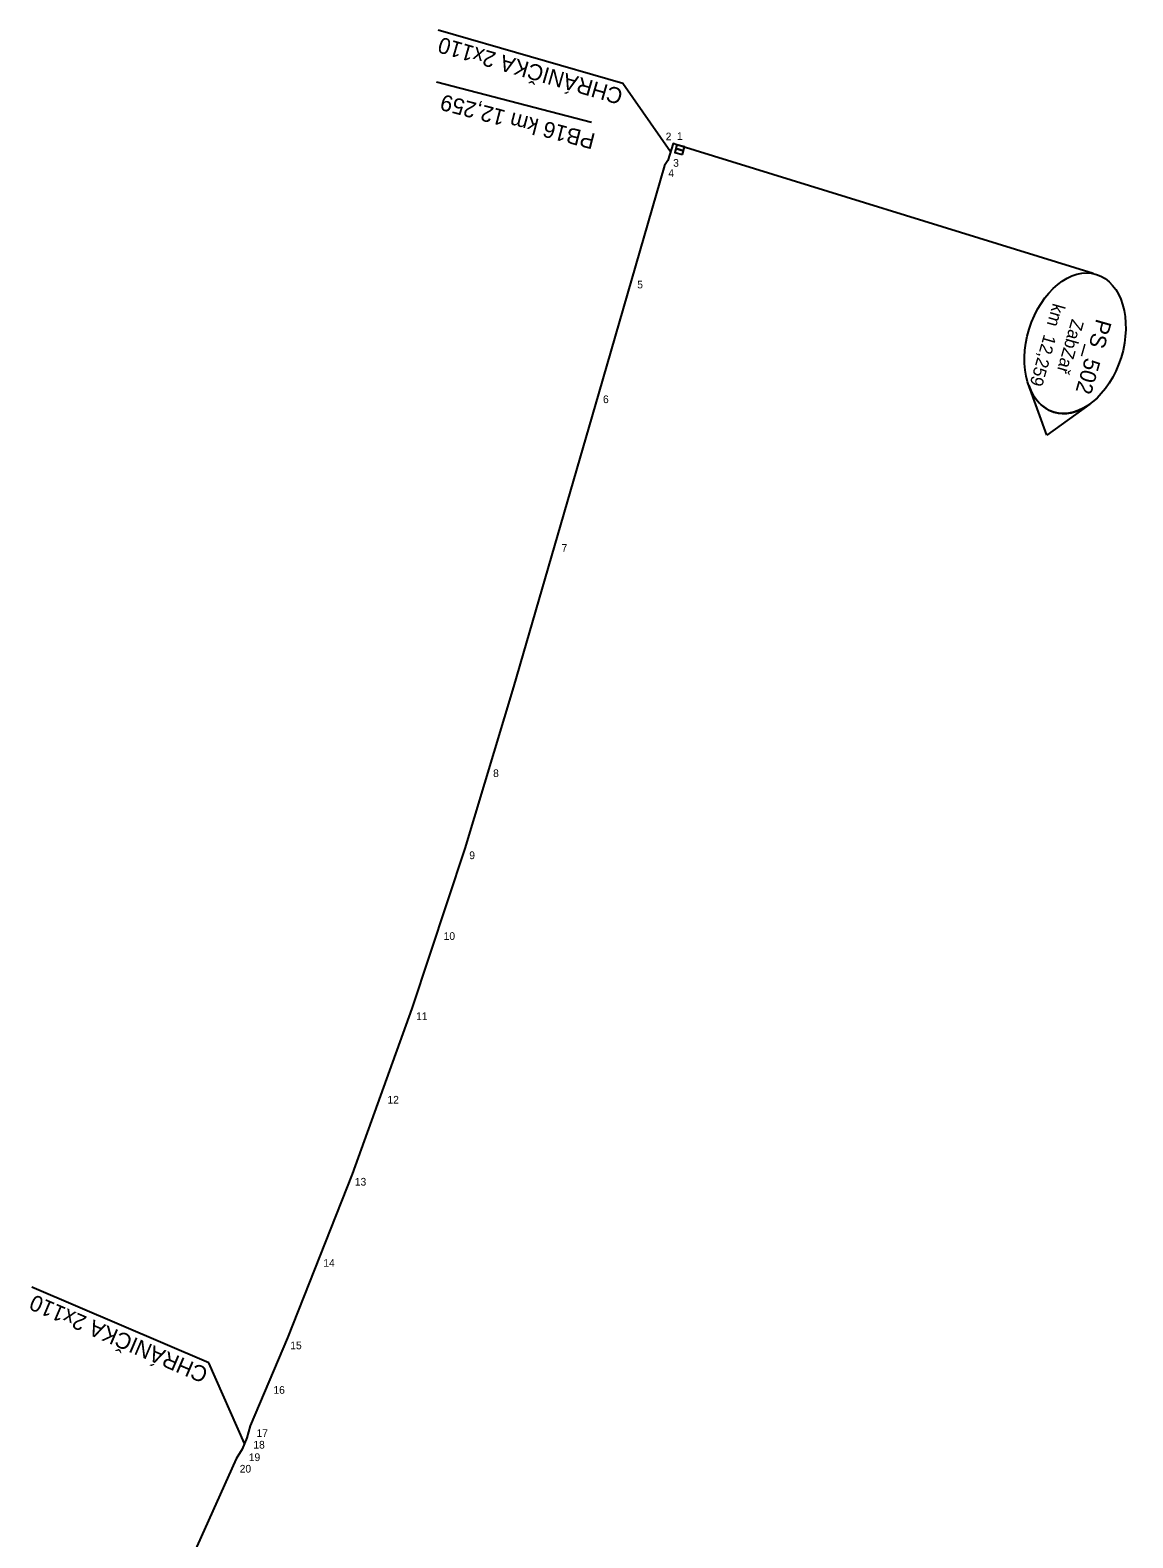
# Model space of a CAD drawing. Extents: x -743397 to -742769, y -1127804 to -1126284.
# Drawn here: x -742941.5 to -742769.4, y -1126665.7 to -1126430.4 of the extents above; entities that cross this region are included whole.
import ezdxf

# ---------------------------------------------------------------- set-up
doc = ezdxf.new("R2010")
doc.units = 0
for name, color, linetype in [('_Násyp', 7, 'Continuous'), ('_Zabezpečovací zařízení', 7, 'Continuous'), ('_Zabezpečovací zařízení_trasa', 7, 'Continuous'), ('bublina_fialová_čára_tenká', 7, 'Continuous'), ('bublina_růžová_230_čára_tučná', 7, 'Continuous'), ('křížky', 7, 'Continuous'), ('Nový stav', 7, 'Continuous'), ('Vrstva 60', 7, 'Continuous')]:
    doc.layers.add(name, color=color, linetype=linetype)

# ---------------------------------------------------------------- blocks, each defined once
blk = doc.blocks.new('POINT_DISPLAY')
blk.add_line((0, 0), (0, 0))

msp = doc.modelspace()

# ---------------------------------------------------------------- linework, layer by layer
at = {"layer": '_Zabezpečovací zařízení'}
for p, q in [((-742840.55, -1126448.27), (-742840.9, -1126449.47)), ((-742840.9, -1126449.47), (-742839.7, -1126449.81)), ((-742840.73, -1126448.87), (-742839.53, -1126449.21)), ((-742839.35, -1126448.61), (-742840.55, -1126448.27)), ((-742839.7, -1126449.81), (-742839.35, -1126448.61))]:
    msp.add_line(p, q, dxfattribs=at)
msp.add_lwpolyline([(-742839.7, -1126449.81), (-742839.53, -1126449.21), (-742840.73, -1126448.87), (-742840.9, -1126449.47), (-742839.7, -1126449.81)], dxfattribs=at)
at = {"layer": '_Zabezpečovací zařízení_trasa'}
msp.add_lwpolyline([(-742840.55, -1126448.27), (-742841.15, -1126448.09), (-742841.97, -1126450.76), (-742842.49, -1126451.53), (-742852.79, -1126487.17), (-742866.03, -1126532.91), (-742873.66, -1126558.12), (-742881.91, -1126583.11), (-742891.24, -1126608.96), (-742901.32, -1126634.54), (-742907.14, -1126648.25), (-742907.64, -1126650.15), (-742908.37, -1126651.89), (-742909.33, -1126653.4), (-742919.08, -1126675.22)], dxfattribs=at)
at = {"layer": 'bublina_fialová_čára_tenká'}
msp.add_line((-742775.61, -1126468.39), (-742840.55, -1126448.27), dxfattribs=at)
at = {"layer": 'bublina_růžová_230_čára_tučná'}
for p, q in [((-742782.86, -1126493.6), (-742785.67, -1126485.84)), ((-742782.86, -1126493.6), (-742785.67, -1126485.84)), ((-742776.16, -1126488.78), (-742782.86, -1126493.6)), ((-742776.16, -1126488.78), (-742782.86, -1126493.6))]:
    msp.add_line(p, q, dxfattribs=at)
msp.add_ellipse((-742778.43, -1126479.27), major_axis=(3.32, 10.75), ratio=0.666667, dxfattribs=at)
msp.add_ellipse((-742778.43, -1126479.27), major_axis=(-3.32, -10.75), ratio=0.666473, start_param=5.557317, end_param=7.009053, dxfattribs=at)
at = {"layer": 'Nový stav'}
for p, q in [((-742848.99, -1126438.74), (-742877.83, -1126430.39)), ((-742848.99, -1126438.74), (-742877.83, -1126430.39)), ((-742853.87, -1126444.83), (-742878.06, -1126438.53)), ((-742853.87, -1126444.83), (-742878.06, -1126438.53)), ((-742841.55, -1126449.4), (-742848.99, -1126438.74)), ((-742841.55, -1126449.4), (-742848.99, -1126438.74)), ((-742913.58, -1126638.41), (-742941.19, -1126626.61)), ((-742913.58, -1126638.41), (-742941.19, -1126626.61)), ((-742908, -1126650.99), (-742913.58, -1126638.41)), ((-742908, -1126650.99), (-742913.58, -1126638.41))]:
    msp.add_line(p, q, dxfattribs=at)
at = {"layer": 'Vrstva 60'}
for p, q in [((-742841.16, -1126448.09), (-742841.16, -1126448.09)), ((-742840.55, -1126448.27), (-742840.55, -1126448.27)), ((-742842.48, -1126451.53), (-742842.48, -1126451.53)), ((-742841.97, -1126450.76), (-742841.97, -1126450.76)), ((-742847.64, -1126469.35), (-742847.64, -1126469.35)), ((-742852.79, -1126487.17), (-742852.79, -1126487.17)), ((-742859.41, -1126510.04), (-742859.41, -1126510.04)), ((-742869.85, -1126545.52), (-742869.85, -1126545.52)), ((-742873.66, -1126558.12), (-742873.66, -1126558.12)), ((-742877.78, -1126570.62), (-742877.78, -1126570.62)), ((-742881.91, -1126583.11), (-742881.91, -1126583.11)), ((-742886.57, -1126596.04), (-742886.57, -1126596.04)), ((-742891.24, -1126608.96), (-742891.24, -1126608.96)), ((-742896.28, -1126621.75), (-742896.28, -1126621.75)), ((-742901.32, -1126634.54), (-742901.32, -1126634.54)), ((-742904.23, -1126641.4), (-742904.23, -1126641.4)), ((-742907.14, -1126648.25), (-742907.14, -1126648.25)), ((-742908.37, -1126651.89), (-742908.37, -1126651.89)), ((-742907.65, -1126650.15), (-742907.65, -1126650.15)), ((-742909.33, -1126653.4), (-742909.33, -1126653.4))]:
    msp.add_line(p, q, dxfattribs=at)

# ---------------------------------------------------------------- block references
at = {"layer": 'křížky', "xscale": 10, "yscale": 10, "rotation": 61.14491455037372}
for p in [(-742841.16, -1126448.09), (-742840.55, -1126448.27), (-742842.48, -1126451.53), (-742841.97, -1126450.76), (-742847.64, -1126469.35), (-742852.79, -1126487.17), (-742859.41, -1126510.04), (-742869.85, -1126545.52), (-742873.66, -1126558.12), (-742877.78, -1126570.62), (-742881.91, -1126583.11), (-742886.57, -1126596.04), (-742891.24, -1126608.96), (-742896.28, -1126621.75), (-742901.32, -1126634.54), (-742904.23, -1126641.4), (-742907.14, -1126648.25), (-742908.37, -1126651.89), (-742907.65, -1126650.15), (-742909.33, -1126653.4)]:
    msp.add_blockref('POINT_DISPLAY', p, dxfattribs=at)

# ---------------------------------------------------------------- texts
at = {"layer": '_Násyp'}
for s, height, p in [('km  12,259', 2, (-742781.88, -1126472.92)), ('ZabZař', 2, (-742778.94, -1126475.38)), ('PS_502', 2.5, (-742775.1, -1126475.33))]:
    msp.add_text(s, height=height, rotation=253.9997, dxfattribs=at).set_placement(p)
at = {"layer": 'Nový stav'}
for s, rotation, p in [('CHRÁNIČKA 2x110', 163.8668, (-742848.8, -1126439.67)), ('CHRÁNIČKA 2x110', 163.8668, (-742848.8, -1126439.67)), ('PB16 km 12,259', 165.395, (-742853.13, -1126446.61)), ('PB16 km 12,259', 165.395, (-742853.13, -1126446.61)), ('CHRÁNIČKA 2x110', 156.8668, (-742913.5, -1126639.36)), ('CHRÁNIČKA 2x110', 156.8668, (-742913.5, -1126639.36))]:
    msp.add_text(s, height=2.5, rotation=rotation, dxfattribs=at).set_placement(p)
at = {"layer": 'Vrstva 60'}
for s, p in [('2', (-742842.31, -1126447.59)), ('1', (-742840.55, -1126447.53)), ('3', (-742841.14, -1126451.72)), ('4', (-742841.9, -1126453.31)), ('5', (-742846.75, -1126470.7)), ('6', (-742852.09, -1126488.61)), ('7', (-742858.55, -1126511.81)), ('8', (-742869.23, -1126546.98)), ('9', (-742872.95, -1126559.79)), ('10', (-742876.95, -1126572.4)), ('11', (-742881.25, -1126584.91)), ('12', (-742885.72, -1126597.95)), ('13', (-742890.81, -1126610.75)), ('14', (-742895.72, -1126623.43)), ('15', (-742900.88, -1126636.3)), ('16', (-742903.51, -1126643.25)), ('17', (-742906.14, -1126649.98)), ('18', (-742906.64, -1126651.8)), ('20', (-742908.77, -1126655.55)), ('19', (-742907.35, -1126653.75))]:
    msp.add_text(s, height=1.2, dxfattribs=at).set_placement(p)

doc.saveas('drawing.dxf')
